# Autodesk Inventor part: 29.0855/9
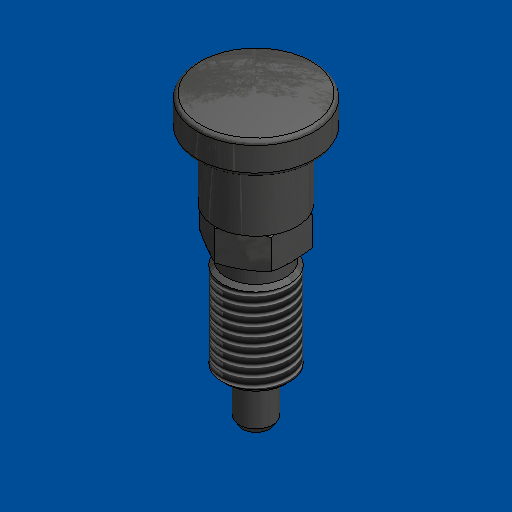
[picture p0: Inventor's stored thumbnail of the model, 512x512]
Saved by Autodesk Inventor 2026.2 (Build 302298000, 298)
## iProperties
Part Number: 29.0855/9
Material: Steel
Description: Spring Plunger M16
Document SubType Name: Modeling
Designer: amoles
Appearance: Plate
Mass: 135.616 g
Surface Area: 47.8992 cm^2
Volume: 17.2759 cm^3
Density: 7.85 g/cm^3
Vendor: S
Author: amoles
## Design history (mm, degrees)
feature "Indexing plunger with rest position GN 817-8-12-C(0)-1"
thread "Thread1" dims "d0" = 31.75, "d1" = 0
body "Solid1"
